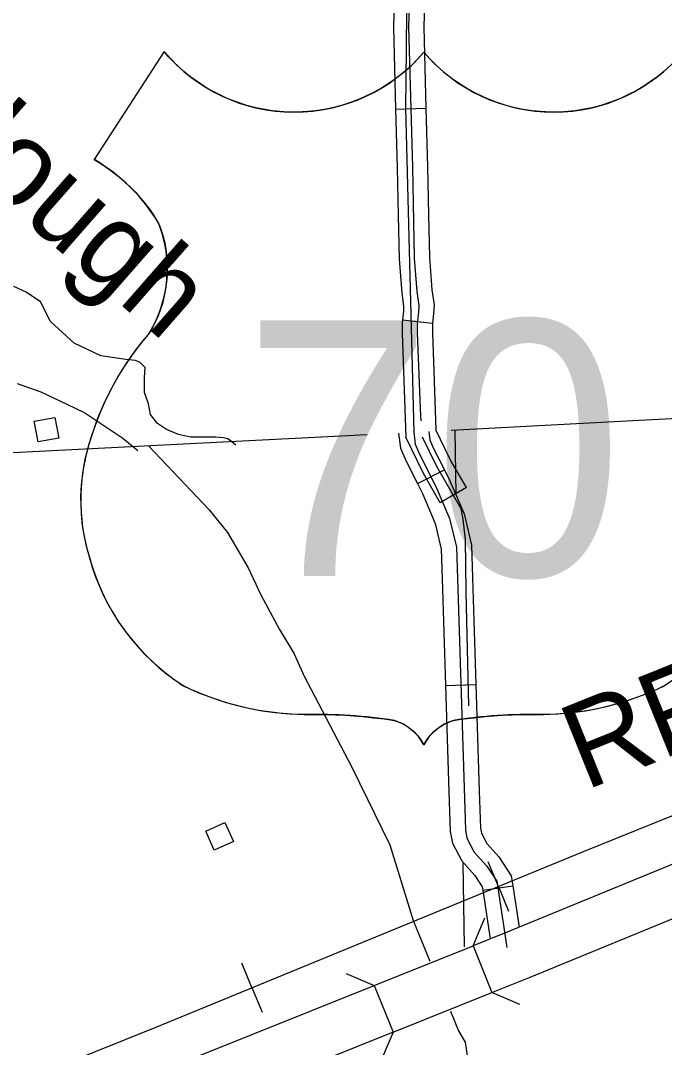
# Model space of a CAD drawing. Extents: x 1084508 to 1142749, y 1057638 to 1093403.
# Drawn here: x 1107154 to 1108155, y 1076523 to 1078120 of the extents above; entities that cross this region are included whole.
import ezdxf

# ---------------------------------------------------------------- set-up
doc = ezdxf.new("R2010")
doc.units = 0
for name, color, linetype in [('Level 15', 7, 'Continuous'), ('Level 2', 7, 'Continuous'), ('Level 22', 7, 'Continuous'), ('Level 35', 7, 'Continuous'), ('Level 37', 7, 'Continuous'), ('Level 40', 7, 'Continuous'), ('Level 45', 7, 'Continuous'), ('Level 47', 7, 'Continuous'), ('Level 5', 7, 'Continuous'), ('Level 56', 7, 'Continuous')]:
    doc.layers.add(name, color=color, linetype=linetype)

msp = doc.modelspace()

# ---------------------------------------------------------------- linework, layer by layer
at = {"layer": 'Level 15'}
for p, q in [((1107857.5, 1076680.7), (1107886.9, 1076607.9)), ((1107703.7, 1076619), (1107733, 1076546.2))]:
    msp.add_line(p, q, dxfattribs=at)
for points in [[(1108732.4, 1077037.2), (1108250, 1076841.6), (1107916.7, 1076704.4), (1107857.5, 1076680.7)], [(1107886.9, 1076607.9), (1107946.2, 1076631.7), (1108279.7, 1076768.9), (1108761.9, 1076964.5)], [(1107703.7, 1076619), (1107857.5, 1076680.7)], [(1105625.1, 1075787), (1106164.3, 1075998.6), (1107029.9, 1076348.6), (1107703.7, 1076619)], [(1107733, 1076546.2), (1107886.9, 1076607.9)], [(1107733, 1076546.2), (1107059.2, 1076275.8), (1106193.3, 1075925.7), (1105655.4, 1075714.6), (1105654.3, 1075714.1)]]:
    msp.add_lwpolyline(points, dxfattribs=at)
at = {"layer": 'Level 2'}
for points in [[(1109501.3, 1077293.7), (1109497.2, 1077426.4), (1109496.4, 1077452.6), (1109493.9, 1077535.1), (1109492.3, 1077586.4), (1109431.1, 1077582.4), (1108694.2, 1077527.3), (1108125.8, 1077498), (1107823.4, 1077482.4)], [(1107692.6, 1077475.6), (1107090.6, 1077444.6)]]:
    msp.add_lwpolyline(points, dxfattribs=at)
at = {"layer": 'Level 22'}
msp.add_line((1107377, 1078071.5), (1107268.4, 1077903.5), dxfattribs=at)
for points in [[(1107780.9, 1078070.6), (1107772.7, 1078061.3), (1107764.8, 1078053.2), (1107755.8, 1078044.8), (1107746.1, 1078036.5), (1107736.8, 1078029.3), (1107725.4, 1078021.3), (1107713.3, 1078013.7), (1107699.4, 1078006.1), (1107681.8, 1077998), (1107668.3, 1077992.7), (1107653.1, 1077987.8), (1107639.1, 1077984.1), (1107626.3, 1077981.5), (1107612.7, 1077979.4), (1107600.3, 1077978.1), (1107583.2, 1077977.3), (1107569.3, 1077977.5), (1107557.2, 1077978.2), (1107545.7, 1077979.4), (1107534.1, 1077981.2), (1107519.4, 1077984.2), (1107505.8, 1077987.7), (1107489.3, 1077993.1), (1107475.3, 1077998.6), (1107462.6, 1078004.5), (1107451, 1078010.6), (1107440.2, 1078016.9), (1107428.2, 1078024.8), (1107417.2, 1078032.9), (1107407.7, 1078040.6), (1107399.7, 1078047.7), (1107391.5, 1078055.6), (1107383.5, 1078064.1), (1107377, 1078071.5), (1107268.4, 1077903.5), (1107276.1, 1077898.8), (1107285.4, 1077892.8), (1107294.1, 1077886.6), (1107305.8, 1077877.5), (1107315.1, 1077869.4), (1107323.4, 1077861.7), (1107331.8, 1077853.2), (1107340.4, 1077843.6), (1107346.6, 1077836.1), (1107352.7, 1077828.3), (1107358.9, 1077819.6), (1107364.9, 1077810.5), (1107370.4, 1077799.9), (1107374.7, 1077786.8), (1107377.9, 1077773.8), (1107380.3, 1077759.9), (1107381.6, 1077747), (1107382, 1077734.6), (1107381.7, 1077723), (1107380.9, 1077713.6), (1107379.4, 1077702.2), (1107377.3, 1077691.4), (1107374.3, 1077679.8), (1107371, 1077669.5), (1107366.5, 1077658.1), (1107359.4, 1077643.2), (1107352.2, 1077631.6), (1107343.4, 1077621.1), (1107332.8, 1077607.5), (1107324.2, 1077595.5), (1107316.1, 1077583.5), (1107308.7, 1077571.8), (1107302.5, 1077561.2), (1107297.1, 1077551.4), (1107290.9, 1077539.6), (1107284.4, 1077525.9), (1107278.5, 1077512.5), (1107274.4, 1077502.6), (1107269.6, 1077489.8), (1107264.3, 1077474.1), (1107260.1, 1077461.1), (1107256.2, 1077446.9), (1107252.5, 1077430.4), (1107250.1, 1077415.7), (1107248.3, 1077400.4), (1107247.3, 1077383.7), (1107247.3, 1077368), (1107248, 1077352.6), (1107249.8, 1077334.6), (1107252.6, 1077317.5), (1107255.5, 1077304.6), (1107258.4, 1077293.3), (1107262.1, 1077280.4), (1107267.1, 1077264.5), (1107274.3, 1077245.1), (1107280.5, 1077230.9), (1107287.6, 1077216.2), (1107295.5, 1077201.9), (1107305.7, 1077185.3), (1107316.3, 1077170.2), (1107326.6, 1077157), (1107338.2, 1077143.5), (1107353.2, 1077127.9), (1107366, 1077116.1), (1107379.1, 1077105.1)], [(1108162.2, 1078047.7), (1108154.2, 1078040.6), (1108144.7, 1078032.9), (1108133.7, 1078024.8), (1108121.7, 1078016.9), (1108110.9, 1078010.6), (1108099.3, 1078004.5), (1108086.6, 1077998.6), (1108072.6, 1077993.1), (1108056, 1077987.7), (1108042.5, 1077984.2), (1108027.8, 1077981.2), (1108016.2, 1077979.4), (1108004.7, 1077978.2), (1107992.6, 1077977.5), (1107978.7, 1077977.3), (1107961.6, 1077978.1), (1107949.2, 1077979.4), (1107935.6, 1077981.5), (1107922.7, 1077984.1), (1107908.8, 1077987.8), (1107893.5, 1077992.7), (1107880, 1077998), (1107862.5, 1078006.1), (1107848.6, 1078013.7), (1107836.4, 1078021.3), (1107825.1, 1078029.3), (1107815.8, 1078036.5), (1107806.1, 1078044.8), (1107797.1, 1078053.2), (1107789.2, 1078061.3), (1107780.9, 1078070.6)], [(1107379.1, 1077105.1), (1107392.7, 1077094.8), (1107409.1, 1077084.1), (1107429.6, 1077074.9), (1107453.7, 1077065.6), (1107473.3, 1077059.3), (1107491, 1077054.4), (1107511, 1077049.8), (1107529.7, 1077046.3), (1107549.9, 1077043.5), (1107575.3, 1077041.3), (1107594.7, 1077040.7), (1107611.4, 1077040.7), (1107627.6, 1077040.6), (1107643.7, 1077040.1), (1107659.1, 1077039.3), (1107672.5, 1077038.4), (1107685.7, 1077037.3), (1107702.5, 1077035.5), (1107719, 1077033.5), (1107728.9, 1077032.1), (1107737.1, 1077030.5), (1107747, 1077026.4), (1107752.7, 1077023.3), (1107757.6, 1077020), (1107764.4, 1077014.5), (1107770.9, 1077008), (1107776.2, 1077001.2), (1107780.9, 1076993.3)], [(1107780.9, 1076993.3), (1107785.7, 1077001.2), (1107791, 1077008), (1107797.5, 1077014.5), (1107804.3, 1077020), (1107809.2, 1077023.3), (1107814.9, 1077026.4), (1107824.8, 1077030.5), (1107832.9, 1077032.1), (1107842.8, 1077033.5), (1107859.3, 1077035.5), (1107876.2, 1077037.3), (1107889.4, 1077038.4), (1107902.8, 1077039.3), (1107918.1, 1077040.1), (1107934.3, 1077040.6), (1107950.5, 1077040.7), (1107967.1, 1077040.7), (1107986.6, 1077041.3), (1108012, 1077043.5), (1108032.2, 1077046.3), (1108050.9, 1077049.8), (1108070.9, 1077054.4), (1108088.5, 1077059.3), (1108108.2, 1077065.6), (1108132.2, 1077074.9), (1108152.8, 1077084.1), (1108169.2, 1077094.8)]]:
    msp.add_lwpolyline(points, dxfattribs=at)
for centre, radius, start, end in [((1107579.4, 1078241.7), 264.4, 220.075, 319.6701), ((1107982.5, 1078241.7), 264.4, 220.3299, 319.925), ((1107126.4, 1077659.5), 282.3, 30.7809, 59.9883), ((1107188.5, 1077734), 193.5, 328.8105, 21.2108), ((1107694.5, 1077337.3), 451.5, 138.9565, 162.6913), ((1107545.5, 1077374.3), 298.3, 160.9576, 197.3819), ((1107594.1, 1077375.1), 345.2, 195.1074, 237.1312), ((1107600.5, 1077483.9), 443.2, 244.0771, 269.5779), ((1107961.4, 1077483.9), 443.2, 270.4221, 295.9229), ((1107610.7, 1076228.8), 811.9, 81.1942, 90.9539), ((1107951.1, 1076228.8), 811.9, 89.0461, 98.8058), ((1107712.3, 1076956.8), 77.8, 28.0342, 72.9864), ((1107849.6, 1076956.8), 77.8, 107.0136, 151.9658)]:
    msp.add_arc(centre, radius, start, end, dxfattribs=at)
at = {"layer": 'Level 35'}
for points in [[(1107353.4, 1077457.9), (1107446.9, 1077358.9), (1107475.5, 1077323.4), (1107507.6, 1077268.7), (1107527.5, 1077226.5), (1107556.3, 1077172.9), (1107579.1, 1077134.6), (1107594.2, 1077100.9), (1107669.2, 1076958.4), (1107727.9, 1076837.6), (1107764.4, 1076719.8), (1107790.2, 1076657)], [(1107822.2, 1076579), (1107834.8, 1076548.5), (1107845, 1076531), (1107849, 1076506.3)]]:
    msp.add_lwpolyline(points, dxfattribs=at)
at = {"layer": 'Level 37'}
for points in [[(1107857.5, 1076680.7), (1107875.9, 1076724)], [(1107660.3, 1076637.4), (1107703.7, 1076619)], [(1107930.2, 1076589.5), (1107886.9, 1076607.9)], [(1107733, 1076546.2), (1107714.6, 1076502.9)]]:
    msp.add_lwpolyline(points, dxfattribs=at)
at = {"layer": 'Level 40'}
for p, q in [((1107896.9, 1076772.8), (1107881.2, 1076811.1)), ((1107896.9, 1076772.8), (1107912.6, 1076734.5)), ((1107513.5, 1076615.6), (1107497.8, 1076653.9)), ((1107513.5, 1076615.6), (1107529.3, 1076577.3))]:
    msp.add_line(p, q, dxfattribs=at)
for points in [[(1102589.2, 1074527.3), (1102597.4, 1074567.1), (1102602.3, 1074584.3), (1102615.4, 1074608.8), (1102622, 1074621.1), (1102633.7, 1074633.9), (1102642.5, 1074641.8), (1102655.3, 1074651.2), (1102670.3, 1074660.7), (1102686.8, 1074670.6), (1102691.4, 1074673), (1102713.6, 1074682.8), (1103674.9, 1075072.8), (1104177.2, 1075277), (1105095.7, 1075646.6), (1105756.1, 1075909.8), (1106326.7, 1076137.2), (1106838.1, 1076342.7), (1107365.6, 1076554.9), (1108026.7, 1076826.1), (1108704.6, 1077100.1), (1109222.4, 1077314), (1109497.3, 1077426.3)], [(1102589.2, 1074527.3), (1102597.4, 1074567.1), (1102602.3, 1074584.3), (1102615.4, 1074608.8), (1102622, 1074621.1), (1102633.7, 1074633.9), (1102642.5, 1074641.8), (1102655.3, 1074651.2), (1102670.3, 1074660.7), (1102686.8, 1074670.6), (1102691.4, 1074673), (1102713.6, 1074682.8), (1103674.9, 1075072.8), (1104177.2, 1075277), (1105095.7, 1075646.6), (1105756.1, 1075909.8), (1106326.7, 1076137.2), (1106838.1, 1076342.7), (1107365.6, 1076554.9), (1108026.7, 1076826.1), (1108704.6, 1077100.1)]]:
    msp.add_lwpolyline(points, dxfattribs=at)
at = {"layer": 'Level 45'}
for p, q in [((1107737.1, 1077982.1), (1107784.2, 1077983.4)), ((1107747.7, 1077654.3), (1107794.5, 1077649.3)), ((1107770.9, 1077399.9), (1107812.9, 1077421.1)), ((1107847.3, 1077393.3), (1107806.5, 1077369.7)), ((1107814.8, 1077085.8), (1107861.8, 1077087.3)), ((1107872.7, 1076767), (1107919.3, 1076774.1))]:
    msp.add_line(p, q, dxfattribs=at)
for points in [[(1107342.4, 1078314.3), (1107572.6, 1078313.9), (1107708.7, 1078316.7), (1107755.6, 1078317.2), (1107753.7, 1078075.4), (1107752.6, 1077983.8), (1107760.6, 1077661.9), (1107765.2, 1077479.4)], [(1107757.2, 1078313.4), (1107760.8, 1078304), (1107762, 1078254.9), (1107757.2, 1078109.4), (1107763.1, 1077891.8), (1107766.1, 1077750.4), (1107770.2, 1077698.3), (1107773.2, 1077676.5), (1107772.6, 1077665.8), (1107770.8, 1077649.3), (1107770.8, 1077633.9), (1107775.5, 1077503.8), (1107776.2, 1077497)], [(1107735, 1078149.2), (1107733.7, 1078109.5), (1107737.1, 1077982.1)], [(1107782, 1078147.6), (1107780.8, 1078109.4), (1107784.2, 1077983.4)], [(1107737.1, 1077982.1), (1107739.6, 1077891.2), (1107741.2, 1077816.6)], [(1107784.2, 1077983.4), (1107786.7, 1077892.3), (1107788.2, 1077817.5)], [(1107741.2, 1077816.6), (1107742.6, 1077749.2), (1107746.8, 1077695.8), (1107749.5, 1077675.5), (1107749.1, 1077667.7), (1107747.7, 1077654.3)], [(1107788.2, 1077817.5), (1107789.6, 1077751.5), (1107793.6, 1077700.9), (1107796.8, 1077677.4), (1107796.1, 1077663.9), (1107794.5, 1077649.3)], [(1107747.7, 1077654.3), (1107747.3, 1077650.5), (1107747.3, 1077633.5), (1107753.1, 1077471.7)], [(1107794.5, 1077649.3), (1107794.3, 1077648), (1107794.3, 1077634.3), (1107799.8, 1077483.2)], [(1107847.3, 1077393.3), (1107821.9, 1077437.1), (1107799.8, 1077483.2)], [(1107741.6, 1077478.2), (1107744.7, 1077454.9), (1107752.9, 1077435.5), (1107770.9, 1077399.9)], [(1107806.5, 1077369.7), (1107780.3, 1077415.1), (1107753.1, 1077471.7)], [(1107765.2, 1077479.4), (1107767.6, 1077461.1), (1107774.3, 1077445.4), (1107800.2, 1077393.9), (1107821, 1077345.1), (1107831.5, 1077300.5), (1107845.5, 1076861.1), (1107847.9, 1076848.3), (1107859.3, 1076826.1), (1107878.9, 1076804.6), (1107894.4, 1076781.1), (1107910.2, 1076678)], [(1107850.7, 1077053.9), (1107846.9, 1077231.4), (1107845.9, 1077312.5), (1107842.1, 1077344), (1107839.2, 1077360.2), (1107801.1, 1077426.1), (1107779.1, 1077471.9)], [(1107788.8, 1077480.6), (1107790.5, 1077467.4), (1107795.7, 1077455.3), (1107812.9, 1077421.1)], [(1107812.9, 1077421.1), (1107821.6, 1077403.9), (1107843.4, 1077352.5), (1107855, 1077303.6), (1107856.6, 1077252.9)], [(1107770.9, 1077399.9), (1107778.9, 1077384), (1107798.5, 1077337.7), (1107808.1, 1077297.4), (1107809.5, 1077251.5)], [(1107809.5, 1077251.5), (1107814.8, 1077085.8)], [(1107856.6, 1077252.9), (1107861.8, 1077087.3)], [(1107814.8, 1077085.8), (1107820, 1076920.2)], [(1107861.8, 1077087.3), (1107867.1, 1076921.7)], [(1107820, 1076920.2), (1107822, 1076858.5), (1107825.4, 1076840.5), (1107839.8, 1076812.6), (1107860.2, 1076790.2), (1107871.9, 1076772.4), (1107872.7, 1076767)], [(1107867.1, 1076921.7), (1107868.9, 1076863.7), (1107870.4, 1076856.1), (1107878.8, 1076839.7), (1107897.5, 1076819.1), (1107916.9, 1076789.7), (1107919.3, 1076774.1)], [(1107872.7, 1076767), (1107884.3, 1076691.5)], [(1107919.3, 1076774.1), (1107929.1, 1076709.6)]]:
    msp.add_lwpolyline(points, dxfattribs=at)
at = {"layer": 'Level 47'}
for points in [[(1107488.4, 1077459.5), (1107488.1, 1077460), (1107482.4, 1077464.6), (1107476.3, 1077469.2), (1107469.1, 1077470.8), (1107457.3, 1077471.8), (1107443.9, 1077471.8), (1107417.8, 1077471.8), (1107399.3, 1077475.9), (1107380.8, 1077483.6), (1107366.9, 1077492.9), (1107355.6, 1077507.2), (1107352.6, 1077523.7), (1107346.4, 1077541.1), (1107346.4, 1077564.8), (1107347.4, 1077580.2), (1107339.7, 1077587.9), (1107332.5, 1077591), (1107317.6, 1077592.5), (1107278.6, 1077598.2), (1107237, 1077618.2), (1107200.1, 1077651.6), (1107184.7, 1077682.4), (1107162.6, 1077697.3), (1107143.1, 1077706)], [(1107148.4, 1077555.5), (1107185.4, 1077542.2), (1107237.7, 1077517.5)], [(1107237.7, 1077517.5), (1107253.6, 1077509.8), (1107313, 1077470.3), (1107335.9, 1077451.1)]]:
    msp.add_lwpolyline(points, dxfattribs=at)
at = {"layer": 'Level 5'}
for points in [[(1107828.9, 1077482.7), (1107830.8, 1077382.2)], [(1107841.5, 1076809.3), (1107843.9, 1076679.2)]]:
    msp.add_lwpolyline(points, dxfattribs=at)
at = {"layer": 'Level 56'}
for points in [[(1107213.1, 1077470.3), (1107180.9, 1077464.5), (1107175.1, 1077496.7), (1107207.2, 1077502.6)], [(1107455.1, 1076829.5), (1107441.7, 1076859.2), (1107471.5, 1076872.7), (1107485, 1076843)]]:
    msp.add_lwpolyline(points, close=True, dxfattribs=at)

# ---------------------------------------------------------------- texts
at = {"layer": 'Level 22'}
msp.add_text('70', height=397.75, dxfattribs=at).set_placement((1107499.6, 1077255.7))
at = {"layer": 'Level 35'}
msp.add_text('Slough', height=132.58, rotation=318.7978, dxfattribs=at).set_placement((1106961.5, 1077982.2))
at = {"layer": 'Level 40'}
msp.add_text('RR.', height=132.58, rotation=21.96, dxfattribs=at).set_placement((1108031.6, 1076921.7))

doc.saveas('drawing.dxf')
